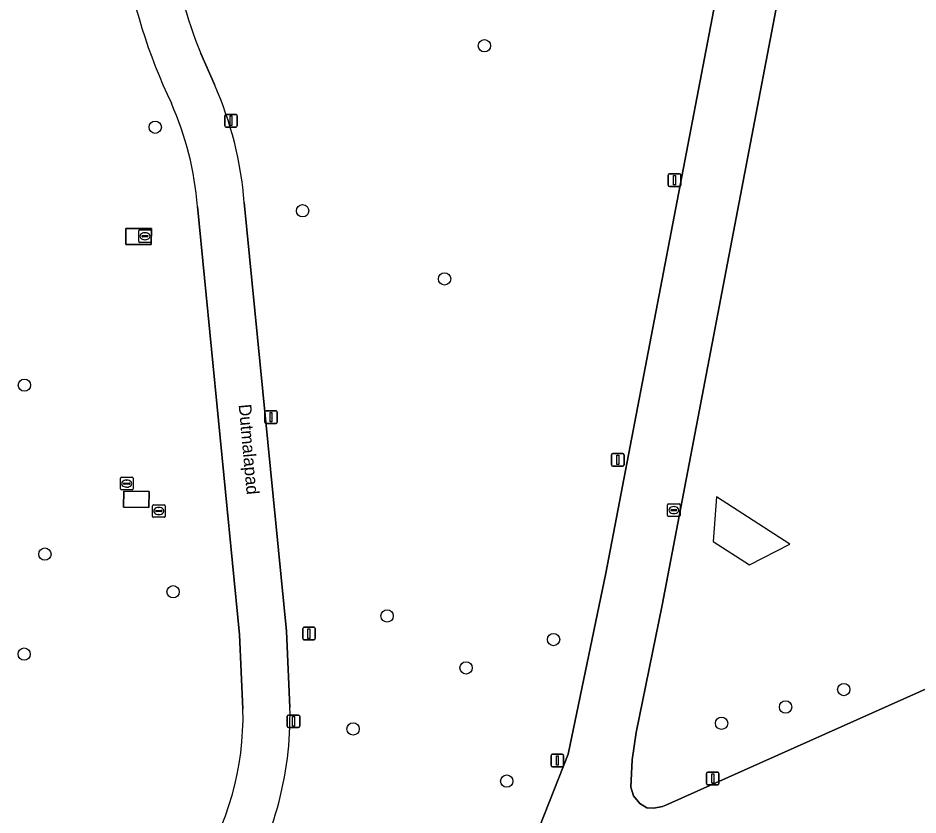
# Model space of a CAD drawing. Extents: x 161477 to 163040, y 383680 to 384871.
# Drawn here: x 161683.5 to 161755, y 384191.4 to 384254.7 of the extents above; entities that cross this region are included whole.
import ezdxf

# ---------------------------------------------------------------- set-up
doc = ezdxf.new("R2010")
doc.units = 0
for name, color, linetype in [('IMGEO_Boom', 7, 'Continuous'), ('IMGEO_Fietspad_gesloten', 7, 'Continuous'), ('IMGEO_Groenvoorziening', 7, 'Continuous'), ('IMGEO_Hek', 7, 'Continuous'), ('IMGEO_Lage_trafo', 7, 'Continuous'), ('IMGEO_Lichtmast', 7, 'Continuous'), ('IMGEO_Openbare_ruimte_label', 7, 'Continuous'), ('IMGEO_Rijbaan_lokaal_gesloten', 7, 'Continuous'), ('IMGEO_Rioolput', 7, 'Continuous')]:
    doc.layers.add(name, color=color, linetype=linetype)

msp = doc.modelspace()

# ---------------------------------------------------------------- linework, layer by layer
at = {"layer": 'IMGEO_Boom'}
for centre in [(161720.516, 384252.515), (161694.377, 384246.035), (161706.083, 384239.398), (161717.355, 384233.98), (161683.984, 384225.542), (161685.61, 384212.121), (161695.795, 384209.124), (161712.79, 384207.2), (161726.01, 384205.329), (161683.966, 384204.171), (161719.06, 384203.08), (161749.057, 384201.356), (161744.439, 384199.969), (161710.084, 384198.222), (161739.352, 384198.672), (161722.288, 384194.078)]:
    msp.add_circle(centre, 0.489, dxfattribs=at)
at = {"layer": 'IMGEO_Fietspad_gesloten'}
for points in [[(161699.081, 384249.418), (161697.991, 384251.896)], [(161705.07, 384199.921), (161704.795, 384205.995), (161701.447, 384240.059)], [(161697.731, 384239.729), (161701.073, 384205.729), (161701.342, 384199.79)]]:
    msp.add_lwpolyline(points, dxfattribs=at)
for centre, radius, start, end in [((161736.172, 384267.265), 44.889, 189.13959, 205.49728), ((161736.131, 384267.26), 41.118, 189.25495, 201.94113), ((161672.67, 384237.763), 28.868, 4.56243, 23.81235), ((161672.647, 384237.757), 25.161, 4.49422, 23.87681), ((161678.328, 384199.229), 23.021, 327.00497, 1.39566), ((161678.34, 384199.227), 26.739, 326.99504, 1.48745)]:
    msp.add_arc(centre, radius, start, end, dxfattribs=at)
at = {"layer": 'IMGEO_Groenvoorziening'}
for points in [[(161694.589, 384173.746), (161723.345, 384186.557), (161727.178, 384196.211), (161730.158, 384210.609), (161739.941, 384261.637)], [(161743.899, 384256.603), (161734.622, 384208.06), (161732.563, 384197.955), (161732.263, 384195.783), (161732.137, 384193.594), (161732.352, 384192.911), (161732.858, 384192.304), (161733.427, 384191.95), (161733.971, 384191.937), (161734.654, 384192.051), (161734.934, 384192.171), (161765.263, 384205.726)], [(161697.991, 384251.896), (161699.081, 384249.418)], [(161701.447, 384240.059), (161704.795, 384205.995), (161705.07, 384199.921)], [(161701.342, 384199.79), (161701.073, 384205.729), (161697.731, 384239.729)]]:
    msp.add_lwpolyline(points, dxfattribs=at)
for points in [[(161694.067, 384237.988), (161694.062, 384236.708), (161692.043, 384236.716), (161692.048, 384237.996)], [(161693.894, 384217.1), (161693.88, 384215.82), (161691.855, 384215.843), (161691.869, 384217.123)]]:
    msp.add_lwpolyline(points, close=True, dxfattribs=at)
for centre, radius, start, end in [((161736.172, 384267.265), 44.889, 189.13959, 205.49728), ((161736.131, 384267.26), 41.118, 189.25495, 201.94113), ((161672.67, 384237.763), 28.868, 4.56243, 23.81235), ((161672.647, 384237.757), 25.161, 4.49422, 23.87681), ((161678.328, 384199.229), 23.021, 327.00497, 1.39566), ((161678.34, 384199.227), 26.739, 326.99504, 1.48745)]:
    msp.add_arc(centre, radius, start, end, dxfattribs=at)
at = {"layer": 'IMGEO_Hek'}
for points in [[(161738.943, 384216.656), (161738.676, 384213.113)], [(161744.775, 384212.914), (161738.943, 384216.656)], [(161738.676, 384213.113), (161741.56, 384211.276)], [(161741.56, 384211.276), (161744.775, 384212.914)]]:
    msp.add_lwpolyline(points, dxfattribs=at)
at = {"layer": 'IMGEO_Lage_trafo'}
for points in [[(161694.062, 384236.708), (161694.067, 384237.988), (161692.048, 384237.996), (161692.043, 384236.716)], [(161693.88, 384215.82), (161693.894, 384217.1), (161691.869, 384217.123), (161691.855, 384215.843)]]:
    msp.add_lwpolyline(points, close=True, dxfattribs=at)
at = {"layer": 'IMGEO_Lichtmast'}
for p, q in [((161699.902, 384246.154), (161699.902, 384246.954)), ((161699.902, 384246.954), (161699.902, 384246.154)), ((161700.002, 384247.054), (161700.792, 384247.054)), ((161700.792, 384247.054), (161700.002, 384247.054)), ((161700.892, 384246.954), (161700.892, 384246.154)), ((161700.892, 384246.154), (161700.892, 384246.954)), ((161700.792, 384246.054), (161700.002, 384246.054)), ((161700.002, 384246.054), (161700.792, 384246.054)), ((161735.117, 384241.435), (161735.117, 384242.235)), ((161735.117, 384242.235), (161735.117, 384241.435)), ((161735.217, 384242.335), (161736.007, 384242.335)), ((161736.007, 384242.335), (161735.217, 384242.335)), ((161736.107, 384242.235), (161736.107, 384241.435)), ((161736.107, 384241.435), (161736.107, 384242.235)), ((161736.007, 384241.335), (161735.217, 384241.335)), ((161735.217, 384241.335), (161736.007, 384241.335)), ((161703.078, 384222.595), (161703.078, 384223.395)), ((161703.078, 384223.395), (161703.078, 384222.595)), ((161703.178, 384223.495), (161703.968, 384223.495)), ((161703.968, 384223.495), (161703.178, 384223.495)), ((161704.068, 384223.395), (161704.068, 384222.595)), ((161704.068, 384222.595), (161704.068, 384223.395)), ((161703.968, 384222.495), (161703.178, 384222.495)), ((161703.178, 384222.495), (161703.968, 384222.495)), ((161730.615, 384219.21), (161730.615, 384220.01)), ((161730.615, 384220.01), (161730.615, 384219.21)), ((161730.715, 384220.11), (161731.505, 384220.11)), ((161731.505, 384220.11), (161730.715, 384220.11)), ((161731.605, 384220.01), (161731.605, 384219.21)), ((161731.605, 384219.21), (161731.605, 384220.01)), ((161731.505, 384219.11), (161730.715, 384219.11)), ((161730.715, 384219.11), (161731.505, 384219.11)), ((161706.085, 384205.4), (161706.085, 384206.2)), ((161706.085, 384206.2), (161706.085, 384205.4)), ((161706.185, 384206.3), (161706.975, 384206.3)), ((161706.975, 384206.3), (161706.185, 384206.3)), ((161707.075, 384206.2), (161707.075, 384205.4)), ((161707.075, 384205.4), (161707.075, 384206.2)), ((161706.975, 384205.3), (161706.185, 384205.3)), ((161706.185, 384205.3), (161706.975, 384205.3)), ((161704.856, 384198.433), (161704.856, 384199.233)), ((161704.856, 384199.233), (161704.856, 384198.433)), ((161704.956, 384199.333), (161705.746, 384199.333)), ((161705.746, 384199.333), (161704.956, 384199.333)), ((161705.846, 384199.233), (161705.846, 384198.433)), ((161705.846, 384198.433), (161705.846, 384199.233)), ((161705.746, 384198.333), (161704.956, 384198.333)), ((161704.956, 384198.333), (161705.746, 384198.333)), ((161725.815, 384195.316), (161725.815, 384196.116)), ((161725.815, 384196.116), (161725.815, 384195.316)), ((161725.915, 384196.216), (161726.705, 384196.216)), ((161726.705, 384196.216), (161725.915, 384196.216)), ((161726.805, 384196.116), (161726.805, 384195.316)), ((161726.805, 384195.316), (161726.805, 384196.116)), ((161726.705, 384195.216), (161725.915, 384195.216)), ((161725.915, 384195.216), (161726.705, 384195.216)), ((161738.155, 384193.888), (161738.155, 384194.688)), ((161738.155, 384194.688), (161738.155, 384193.888)), ((161738.255, 384194.788), (161739.045, 384194.788)), ((161739.045, 384194.788), (161738.255, 384194.788)), ((161739.145, 384194.688), (161739.145, 384193.888)), ((161739.145, 384193.888), (161739.145, 384194.688)), ((161739.045, 384193.788), (161738.255, 384193.788)), ((161738.255, 384193.788), (161739.045, 384193.788))]:
    msp.add_line(p, q, dxfattribs=at)
for points in [[(161700.322, 384246.929), (161700.472, 384246.929), (161700.472, 384246.179), (161700.322, 384246.179), (161700.322, 384246.929)], [(161735.537, 384242.21), (161735.687, 384242.21), (161735.687, 384241.46), (161735.537, 384241.46), (161735.537, 384242.21)], [(161703.498, 384223.37), (161703.648, 384223.37), (161703.648, 384222.62), (161703.498, 384222.62), (161703.498, 384223.37)], [(161731.035, 384219.985), (161731.185, 384219.985), (161731.185, 384219.235), (161731.035, 384219.235), (161731.035, 384219.985)], [(161706.505, 384206.175), (161706.655, 384206.175), (161706.655, 384205.425), (161706.505, 384205.425), (161706.505, 384206.175)], [(161705.276, 384199.208), (161705.426, 384199.208), (161705.426, 384198.458), (161705.276, 384198.458), (161705.276, 384199.208)], [(161726.235, 384196.091), (161726.385, 384196.091), (161726.385, 384195.341), (161726.235, 384195.341), (161726.235, 384196.091)], [(161738.575, 384194.663), (161738.725, 384194.663), (161738.725, 384193.913), (161738.575, 384193.913), (161738.575, 384194.663)]]:
    msp.add_lwpolyline(points, dxfattribs=at)
for centre, start, end in [((161700.002, 384246.954), 90, 180), ((161700.002, 384246.954), 90, 180), ((161700.792, 384246.954), 0, 90), ((161700.792, 384246.954), 360, 90), ((161700.002, 384246.154), 180, 270), ((161700.002, 384246.154), 180, 270), ((161700.792, 384246.154), 270, 0), ((161700.792, 384246.154), 270, 0), ((161735.217, 384242.235), 90, 180), ((161735.217, 384242.235), 90, 180), ((161736.007, 384242.235), 0, 90), ((161736.007, 384242.235), 360, 90), ((161735.217, 384241.435), 180, 270), ((161735.217, 384241.435), 180, 270), ((161736.007, 384241.435), 270, 0), ((161736.007, 384241.435), 270, 0), ((161703.178, 384223.395), 90, 180), ((161703.178, 384223.395), 90, 180), ((161703.968, 384223.395), 0, 90), ((161703.968, 384223.395), 360, 90), ((161703.178, 384222.595), 180, 270), ((161703.178, 384222.595), 180, 270), ((161703.968, 384222.595), 270, 0), ((161703.968, 384222.595), 270, 0), ((161730.715, 384220.01), 90, 180), ((161730.715, 384220.01), 90, 180), ((161731.505, 384220.01), 0, 90), ((161731.505, 384220.01), 360, 90), ((161730.715, 384219.21), 180, 270), ((161730.715, 384219.21), 180, 270), ((161731.505, 384219.21), 270, 0), ((161731.505, 384219.21), 270, 0), ((161706.185, 384206.2), 90, 180), ((161706.185, 384206.2), 90, 180), ((161706.975, 384206.2), 0, 90), ((161706.975, 384206.2), 360, 90), ((161706.185, 384205.4), 180, 270), ((161706.185, 384205.4), 180, 270), ((161706.975, 384205.4), 270, 0), ((161706.975, 384205.4), 270, 0), ((161704.956, 384199.233), 90, 180), ((161704.956, 384199.233), 90, 180), ((161705.746, 384199.233), 0, 90), ((161705.746, 384199.233), 360, 90), ((161704.956, 384198.433), 180, 270), ((161704.956, 384198.433), 180, 270), ((161705.746, 384198.433), 270, 0), ((161705.746, 384198.433), 270, 0), ((161725.915, 384196.116), 90, 180), ((161725.915, 384196.116), 90, 180), ((161726.705, 384196.116), 0, 90), ((161726.705, 384196.116), 360, 90), ((161725.915, 384195.316), 180, 270), ((161725.915, 384195.316), 180, 270), ((161726.705, 384195.316), 270, 0), ((161726.705, 384195.316), 270, 0), ((161738.255, 384194.688), 90, 180), ((161738.255, 384194.688), 90, 180), ((161739.045, 384194.688), 0, 90), ((161739.045, 384194.688), 360, 90), ((161738.255, 384193.888), 180, 270), ((161738.255, 384193.888), 180, 270), ((161739.045, 384193.888), 270, 0), ((161739.045, 384193.888), 270, 0)]:
    msp.add_arc(centre, 0.1, start, end, dxfattribs=at)
at = {"layer": 'IMGEO_Rijbaan_lokaal_gesloten'}
for points in [[(161733.75, 384274.516), (161730.61, 384275.368), (161728.643, 384275.876), (161728.617, 384275.766), (161728.532, 384275.403), (161728.435, 384275.429), (161727.166, 384270.561), (161727.187, 384270.431), (161727.115, 384270.181), (161727.059, 384269.989), (161728.987, 384269.454), (161735.03, 384268.003), (161737.038, 384267.25), (161738.189, 384266.605), (161739.378, 384265.251), (161739.846, 384264.352), (161740, 384263.58), (161740.086, 384263.15), (161739.941, 384261.637), (161730.158, 384210.609), (161727.178, 384196.211), (161723.345, 384186.557), (161694.589, 384173.746)], [(161765.263, 384205.726), (161734.934, 384192.171), (161734.654, 384192.051), (161733.971, 384191.937), (161733.427, 384191.95), (161732.858, 384192.304), (161732.352, 384192.911), (161732.137, 384193.594), (161732.263, 384195.783), (161732.563, 384197.955), (161734.622, 384208.06), (161743.899, 384256.603)]]:
    msp.add_lwpolyline(points, dxfattribs=at)
at = {"layer": 'IMGEO_Rioolput'}
for p, q in [((161693.137, 384237.878), (161693.989, 384237.878)), ((161693.062, 384236.952), (161693.062, 384237.804)), ((161693.321, 384237.372), (161693.321, 384237.384)), ((161693.759, 384237.335), (161693.361, 384237.335)), ((161693.364, 384237.421), (161693.762, 384237.421)), ((161693.55, 384237.658), (161693.575, 384237.658)), ((161693.805, 384237.384), (161693.805, 384237.372)), ((161694.063, 384237.804), (161694.063, 384236.952)), ((161693.989, 384236.878), (161693.137, 384236.878)), ((161693.573, 384237.098), (161693.548, 384237.098)), ((161691.609, 384217.294), (161691.609, 384218.146)), ((161691.684, 384218.22), (161692.536, 384218.22)), ((161692.097, 384218), (161692.122, 384218)), ((161692.61, 384218.146), (161692.61, 384217.294)), ((161692.536, 384217.22), (161691.684, 384217.22)), ((161691.868, 384217.714), (161691.868, 384217.726)), ((161692.306, 384217.677), (161691.908, 384217.677)), ((161691.911, 384217.763), (161692.309, 384217.763)), ((161692.12, 384217.44), (161692.095, 384217.44)), ((161692.352, 384217.726), (161692.352, 384217.714)), ((161694.159, 384215.114), (161694.159, 384215.966)), ((161694.234, 384216.04), (161695.086, 384216.04)), ((161694.647, 384215.82), (161694.672, 384215.82)), ((161695.16, 384215.966), (161695.16, 384215.114)), ((161735.065, 384215.186), (161735.065, 384216.038)), ((161735.14, 384216.112), (161735.992, 384216.112)), ((161735.553, 384215.892), (161735.578, 384215.892)), ((161736.066, 384216.038), (161736.066, 384215.186)), ((161695.086, 384215.04), (161694.234, 384215.04)), ((161694.418, 384215.534), (161694.418, 384215.546)), ((161694.856, 384215.497), (161694.458, 384215.497)), ((161694.461, 384215.583), (161694.859, 384215.583)), ((161694.67, 384215.26), (161694.645, 384215.26)), ((161694.902, 384215.546), (161694.902, 384215.534)), ((161735.992, 384215.112), (161735.14, 384215.112)), ((161735.324, 384215.606), (161735.324, 384215.618)), ((161735.762, 384215.569), (161735.364, 384215.569)), ((161735.367, 384215.655), (161735.765, 384215.655)), ((161735.576, 384215.332), (161735.551, 384215.332)), ((161735.808, 384215.618), (161735.808, 384215.606))]:
    msp.add_line(p, q, dxfattribs=at)
for points in [[(161693.137, 384237.878), (161693.989, 384237.878)], [(161693.062, 384236.952), (161693.062, 384237.804)], [(161694.063, 384237.804), (161694.063, 384236.952)], [(161693.989, 384236.878), (161693.137, 384236.878)], [(161691.609, 384217.294), (161691.609, 384218.146)], [(161691.684, 384218.22), (161692.536, 384218.22)], [(161692.61, 384218.146), (161692.61, 384217.294)], [(161692.536, 384217.22), (161691.684, 384217.22)], [(161694.159, 384215.114), (161694.159, 384215.966)], [(161694.234, 384216.04), (161695.086, 384216.04)], [(161695.16, 384215.966), (161695.16, 384215.114)], [(161735.065, 384215.186), (161735.065, 384216.038)], [(161735.14, 384216.112), (161735.992, 384216.112)], [(161736.066, 384216.038), (161736.066, 384215.186)], [(161695.086, 384215.04), (161694.234, 384215.04)], [(161735.992, 384215.112), (161735.14, 384215.112)]]:
    msp.add_lwpolyline(points, dxfattribs=at)
for centre, radius, start, end in [((161693.139, 384237.802), 0.0765, 91.55205, 178.44795), ((161693.139, 384237.802), 0.0765, 91.55205, 178.44795), ((161693.987, 384237.802), 0.0765, 1.55205, 88.44795), ((161693.987, 384237.802), 0.0765, 1.55205, 88.44795), ((161693.361, 384237.381), 0.0403, 85.87752, 175.75265), ((161693.358, 384237.371), 0.0366, 178.93798, 274.71019), ((161693.762, 384237.378), 0.043, 264.86636, 352.45326), ((161693.766, 384237.383), 0.0386, 1.73085, 96.63898), ((161693.139, 384236.954), 0.0765, 181.55205, 268.44795), ((161693.139, 384236.954), 0.0765, 181.55205, 268.44795), ((161693.987, 384236.954), 0.0765, 271.55205, 358.44795), ((161693.987, 384236.954), 0.0765, 271.55205, 358.44795), ((161691.686, 384218.144), 0.0765, 91.55205, 178.44795), ((161691.686, 384218.144), 0.0765, 91.55205, 178.44795), ((161692.534, 384218.144), 0.0765, 1.55205, 88.44795), ((161692.534, 384218.144), 0.0765, 1.55205, 88.44795), ((161691.686, 384217.296), 0.0765, 181.55205, 268.44795), ((161691.686, 384217.296), 0.0765, 181.55205, 268.44795), ((161691.908, 384217.723), 0.0403, 85.87752, 175.75265), ((161691.905, 384217.713), 0.0366, 178.93798, 274.71019), ((161692.309, 384217.72), 0.043, 264.86636, 352.45326), ((161692.313, 384217.725), 0.0386, 1.73085, 96.63898), ((161692.534, 384217.296), 0.0765, 271.55205, 358.44795), ((161692.534, 384217.296), 0.0765, 271.55205, 358.44795), ((161694.236, 384215.964), 0.0765, 91.55205, 178.44795), ((161694.236, 384215.964), 0.0765, 91.55205, 178.44795), ((161695.084, 384215.964), 0.0765, 1.55205, 88.44795), ((161695.084, 384215.964), 0.0765, 1.55205, 88.44795), ((161735.142, 384216.036), 0.0765, 91.55205, 178.44795), ((161735.142, 384216.036), 0.0765, 91.55205, 178.44795), ((161735.99, 384216.036), 0.0765, 1.55205, 88.44795), ((161735.99, 384216.036), 0.0765, 1.55205, 88.44795), ((161694.236, 384215.116), 0.0765, 181.55205, 268.44795), ((161694.236, 384215.116), 0.0765, 181.55205, 268.44795), ((161694.458, 384215.543), 0.0403, 85.87752, 175.75265), ((161694.455, 384215.533), 0.0366, 178.93798, 274.71019), ((161694.859, 384215.54), 0.043, 264.86636, 352.45326), ((161694.863, 384215.545), 0.0386, 1.73085, 96.63898), ((161695.084, 384215.116), 0.0765, 271.55205, 358.44795), ((161695.084, 384215.116), 0.0765, 271.55205, 358.44795), ((161735.142, 384215.188), 0.0765, 181.55205, 268.44795), ((161735.142, 384215.188), 0.0765, 181.55205, 268.44795), ((161735.364, 384215.615), 0.0403, 85.87752, 175.75265), ((161735.361, 384215.605), 0.0366, 178.93798, 274.71019), ((161735.765, 384215.612), 0.043, 264.86636, 352.45326), ((161735.769, 384215.617), 0.0386, 1.73085, 96.63898), ((161735.99, 384215.188), 0.0765, 271.55205, 358.44795), ((161735.99, 384215.188), 0.0765, 271.55205, 358.44795)]:
    msp.add_arc(centre, radius, start, end, dxfattribs=at)
for centre, major_axis, ratio, start_param, end_param in [((161693.549, 384237.378), (-0.387, 0.002), 0.722429, 4.712389, 7.853982), ((161693.574, 384237.378), (-0.39, 0.002), 0.717154, 1.570796, 4.712389), ((161692.096, 384217.72), (-0.387, 0.002), 0.722429, 4.712389, 7.853982), ((161692.121, 384217.72), (-0.39, 0.002), 0.717154, 1.570796, 4.712389), ((161694.646, 384215.54), (-0.387, 0.002), 0.722429, 4.712389, 7.853982), ((161694.671, 384215.54), (-0.39, 0.002), 0.717154, 1.570796, 4.712389), ((161735.552, 384215.612), (-0.387, 0.002), 0.722429, 4.712389, 7.853982), ((161735.577, 384215.612), (-0.39, 0.002), 0.717154, 1.570796, 4.712389)]:
    msp.add_ellipse(centre, major_axis=major_axis, ratio=ratio, start_param=start_param, end_param=end_param, dxfattribs=at)

# ---------------------------------------------------------------- texts
at = {"layer": 'IMGEO_Openbare_ruimte_label'}
msp.add_text('Dutmalapad', height=1, rotation=275.16331, dxfattribs=at).set_placement((161700.998, 384223.99))

doc.saveas('drawing.dxf')
